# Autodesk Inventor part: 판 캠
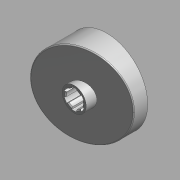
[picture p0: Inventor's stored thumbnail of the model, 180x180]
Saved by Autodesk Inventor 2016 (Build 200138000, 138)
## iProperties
Created: 2015-11
Part Number: 판 캠
Document SubType Name: 모델링
Designer: mdu
Material: 강철, 연강
Density: 7.86 g/cm^3
Mass: 682.455 g
Surface Area: 331.303 cm^2
Volume: 86.8264 cm^3
Appearance: 알루미늄 - 평지
변환 표준: STEP AP214IS
파일 이름: C:\Users\SeoGD\Desktop\?쒗뿕\??stp
전처리기: Build: 253, Release: 2010 SP1 - Date: Wed 07/29/2009
전송 단위: 밀리미터
불확실성: 0.01
Author: mdu
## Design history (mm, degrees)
node "작업 평면4"
sketch "스케치1"
  geometry: C1 r 44.5 at (0, 0); 1 further point
  constraints: 1 centre point, 1 coincident
  dimensions: "d25" = 89 diameter of C1
extrude "돌출1" new body sketch "스케치1" distance "d1" = 40; taper "d2" = 0 deg
sketch "스케치2"
  geometry: L1 (-44.5, 15)-(44.5, 38.847); L2 (-44.5, 0)-(-44.5, 40) reference; L3 (-44.5, 40)-(44.5, 40) reference; L4 (44.5, 0)-(44.5, 40) reference; 1 further point
  constraints: 2 end point, 2 point on line
  dimensions: "d26" = 15 distance of L2.start L1.start; "d27" = 75 deg angle of L1 L2
extrude "돌출2" cut sketch "스케치2" stored distance "d5" = 40; taper "d6" = 0 deg
node "작업 평면1"
sketch "스케치3"
  geometry: C1 r 13 at (0, 0); 1 further point
  constraints: 1 centre point, 1 coincident
  dimensions: "d9" = 26 diameter of C1
extrude "돌출3" join sketch "스케치3" distance "d10" = 38; taper "d11" = 0 deg
hole "구멍1" diameter "d14" = 18; stored, may be unused: countersink angle "d18" = 90 deg, drill point angle "d20" = 118 deg; dims "d12" = 10, "d13" = 10, "d15" = 6, "d16" = 4, "d17" = 2, "d19" = 8
feature "쉘2" dims "d29" = 5
sketch "스케치6"
  geometry: C1 r 17.5 at (0, 0); C2 r 14 at (0, 0) reference; 1 further point
  constraints: 1 centre point, 1 coincident
  dimensions: "d28" = 35 diameter of C1
extrude "돌출4" join sketch "스케치6" stored distance "d30" = 38; taper "d31" = 0 deg
fillet "모깎기1" dims "d32" = 3
chamfer "모따기1" distance "d21" = 1; stored, may be unused: second distance "d22" = 2, angle "d23" = 45 deg
sketch "스케치7"
  geometry: L1 (-12.374, 12.374)-(-27.931, 27.931); A1 r 39.5 centre (0, 0) between (-27.931, 27.931) and (0, 39.5) reference; 2 further points
  constraints: 2 end point, 2 point on circle, 1 point on line, 1 vertical alignment, 2 other
  dimensions: "d33" = 45 deg dimension on point (0, 0) L1.start A1.end
feature "리브1" sketch "스케치7" dims "d34" = 5, "d35" = 1, "d36" = 0
fillet "모깎기2" dims "d37" = 3
sketch "스케치8"
  geometry: L1 (2.5, 10.712)-(2.5, 8.646); L2 (-2.5, 10.712)-(-2.5, 8.646); A1 r 11 centre (0, 0) between (2.5, 10.712) and (-2.5, 10.712); A2 r 9 centre (0, 0) between (2.5, 8.646) and (-2.5, 8.646) reference; 1 further point
  constraints: 4 end point, 4 point on circle, 2 parallel, 1 centre point, 1 coincident, 1 vertical
  dimensions: "d41" = 22 diameter of A1; "d42" = 5 distance between parallel lines of L1 L2
extrude "돌출5" cut sketch "스케치8" stored distance "d43" = 38; taper "d44" = 0 deg
fillet "모깎기3" dims "d48" = 1
node "솔리드1"
node "솔리드 본체"
node "곡면 본체"
pattern_circular "원형 패턴1" dims angle "d39" = 360 deg
pattern_circular "원형 패턴2" dims angle "d46" = 360 deg
node "솔리드2"
